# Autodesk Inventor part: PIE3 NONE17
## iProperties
Shininess: 64.0
Length Units: 11269
Angle Units: 11279
Time Units: 11290
Mass Units: 11286
Length Display Precision: 3
Angle Display Precision: 2
Compacted: True
Part Number: PIE3 NONE17
Document SubType Name: Modeling
Created: 2004-08
Designer: John Blackburn
Manufacturer: Standard
Standards Organization: Custom
Density: 0.0
Volumn: 0.0
Area: 0.0
PropertySet Name: Model Information
Control State: 0
Master: False
Checked Out: False
Author: John Blackburn
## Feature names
1. Erst1
